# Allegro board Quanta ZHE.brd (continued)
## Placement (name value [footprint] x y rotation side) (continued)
TP56  *TP  [TP2050]  42.35 55.42 180 bottom
TP57  *TP  [TP2650]  36.23 47.62 180 bottom
TP58  *TP  [TP2650]  35.72 46.4 180 bottom
TP59  *TP  [TP2650]  25.69 44.88 180 bottom
TP60  *TP  [TP2650]  26.19 43.48 180 bottom
TP61  *TP  [TP2050]  15.78 23.16 180 bottom
TP62  *TP  [TP2050]  72.8 66.22 0 top
TP63  *TP  [TP2050]  43.72 33.86 0 top
U1  AZ1045-04F.R7G  [UDFN10-2_5X1-5]  118.52 94.41 180 top
U2  AZ1045-04F.R7G  [UDFN10-2_5X1-5]  122.46 94.41 180 top
U3  RTL8111H-CG  [QFN32-4X4-4-33P-0_9H]  30.64 89.84 90 top
U4  G524B2T11U  [SOT23-5]  90.2 89.2 180 top
U5  AZ1065-06F.R7G  [DFN10-4_1X2-8-11P]  102.9 88.82 180 top
U6  PS8209AQFN48GTR2-A0  [QFN48-6X6-4-49P-PS8409]  119.67 84.12 90 top
U7  G5245AT11U  [SOT23-5-2_8-95-5P-G708]  155.61 78.66 0 top
U8  AZ1065-06F.R7G  [DFN10-4_1X2-8-11P]  168.94 59.74 90 top
U9  RAM@DDR4_96P  [BGA96-MICRON-MT41J64M16JT-187EG]  137.58 55.11 90 top
U10  *G2129TL1U  [SC70-2_1-65-6P-G2129TL1U]  21.75 44.75 270 top
U11  RTS5170-GRT  [QFN24-4X4-5-25P-ALC5629]  164.88 43.23 270 top
U12  *G9090-180T11U  [TSOT23-2_8-95-5P-G916-475TOUF]  47.15 42.34 90 top
U13  RAM@DDR4_96P  [BGA96-MICRON-MT41J64M16JT-187EG]  137.58 37.33 90 top
U14  IT8987E/BX  [LQFP128-16X16-4-1_6H]  30.51 32.18 270 top
U15  *G923-330T1UF  [SOT23-5]  173.36 31.04 180 top
U16  ALC255-CG  [QFN48-6X6-4-49P-ALC280]  179.48 17.99 0 top
U17  GS@LIS3DHTR  [LGA16-3X3-5]  95.54 13.26 270 top
U18  G524B2T11U  [SOT23-5]  114.97 94.66 180 bottom
U19  AP2331SA-7  [SOT23_213-3_3-2]  118.78 93.39 90 bottom
U20  NS892407  [TRF-15_1X10-1-25P]  40.29 92.12 90 bottom
U21  GD25LB64CSIGR  [SOIC8-7_9-1_27-2_16H]  85.73 88.06 90 bottom
U22  GLK_SOC_RVP1  [BGA1090-INTEL-GEMINI-LAKE]  97.78 63.65 270 bottom
U23  *TPM@G2129TL1U  [SC70-2_1-65-6P-G2129TL1U]  42.07 58.34 0 bottom
U24  G524B2T11U  [SOT23-5]  167.16 55.17 0 bottom
U25  RAM@DDR4_96P  [BGA96-MICRON-MT41J64M16JT-187EG]  137.58 55.11 270 bottom
U26  EM@H26M64103EMR  [BGA153-SANDISK-SDIN7DP4-16G]  62.14 53.49 270 bottom
U27  G753T11U  [SOT23-5-2_8-95-5P-G708]  54.11 54.02 90 bottom
U28  *TPM@NPCT650ABAYX  [QFN32-5X5-5-33P-0_85H]  41.82 51.36 270 bottom
U29  W25X10CLSNIG  [SOIC8-6-1_27]  30.64 45.19 270 bottom
U30  RAM@DDR4_96P  [BGA96-MICRON-MT41J64M16JT-187EG]  137.58 37.33 270 bottom
U31  APL5606AKI-TRG  [SOP8-6-1_27-G5461]  25.69 31.29 90 bottom
U32  PS8527BTQFN20GTR2-A2  [TQFN20-4X4-5-25P]  129.95 24.18 270 bottom
U33  G2129BTL1U  [SC70-2_1-65-6P-G2129TL1U]  42.2 15.67 90 bottom
U34  *MC74VHC1G08DFT2G  [SOT353-1-2_125-65-5P]  61.25 61.9 0 top
Y1  25MHZ/30ppm  [XTL-2_05X1_65-1_4X1_1-0_6H]  30.64 82.47 0 top
Y2  32.768KHZ/20ppm  [XTL-3_2X1_5-2_5-0_8H]  100.49 82.85 0 bottom
Y3  19.2MHZ/20ppm  [XTL-3_2X2_5-2_2X1_7-0_8H]  117.5 68.27 90 bottom

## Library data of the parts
C1 C2 C4-C37 C39 C40 C42-C52 C54-C62 C64 C66 C67 C69-C76 C78 C80-C82 C84-C109 C111-C159 C161-C170 C172-C181 C183-C257 C259-C261 C263-C272 C274-C302 C304-C331 C333-C350 C353-C436 C438-C470 C473-C481 C483-C485 C487 C488 C542 PC1 PC2 PC7-PC11 PC16-PC23 PC25-PC28 PC31-PC33 PC36-PC38 PC41-PC48 PC51 PC56 PC60 PC62-PC64 PC66 PC68-PC72 PC74 PC76-PC78 PC80-PC83 PC85-PC111 PC118-PC128 PC133-PC152 PC155 PC156 PC159-PC165 PC168-PC174 PC177-PC196 PC200 PC211 PC214 PC216 PC220-PC229 PC232-PC235 PC237 = CAP NON-POL_BGM
C3 C38 C41 C53 C63 C65 C68 C77 C79 C83 C110 C258 C262 C273 C437 C471 C472 C482 PC3-PC6 PC12-PC15 PC24 PC29 PC30 PC34 PC35 PC39 PC40 PC49 PC50 PC52-PC55 PC57-PC59 PC61 PC65 PC67 PC73 PC75 PC79 PC84 PC112-PC117 PC129-PC132 PC153 PC154 PC157 PC158 PC166 PC167 PC175 PC176 PC197-PC199 PC201-PC203 PC205-PC210 PC212 PC213 PC215 PC217-PC219 PC230 PC231 PC236 = CAP_NON-POL_BGM
C160 C171 C182 C351 C352 = C_11
C332 = C
CN1 = HDMI_C128H9-K1909-L_19P_BGM
CN2 CN6 = USB3_13P_BGM
CN3 = USB2_8P_BGM
CN4 = RJ45_8P_4F_BGM
CN5 = Housing_40P_6fixP_BGM
CN7 = CON30X1_0
CN8 = COMBOJACK_7P_BGM
CN9 CN13 CN17 = FFCFPC_4P_BGM
CN10 = NGFF_79P_EKEY_NAME_BGM
CN11 = SDCARD_17P_156-2001902600_BGM
CN12 = FFCFPC_8P_BGM
CN14 = RTC_4P_BGM
CN15 = Housing_20P_FIX6P_BGM
CN16 = CON26_0
CP1-CP6 = CAP_8P4R_BGM
D1 D2 D7 D15 D16 D24 D28 D30 D37 D38 D41 = TVS_DIODE_BGM
D3 D4 D6 D8-D11 D14 D17 D18 D21 D22 D26 D27 D31 D32 D35 D36 D39 = Schottky_DIODE_BGM
D5 = DIODE_BGM
D12 D13 D19 D20 D23 D25 = TVS_DIODE_BGM_0
D29 = BAT54C_BGM
D40 EC1-EC6 = Varistor_BGM
ESD2 = AZC099-04S.R_BGM
HE1 = HALL_IC_3P_BGM
HOLE1 HOLE5 HOLE6 HOLE8-HOLE10 = 3x2_0.1
HOLE2-HOLE4 HOLE7 HOLE11-HOLE17 SPAD1-SPAD10 = 3x2_1.1
J1 = OPEN
JDIM1 = DDR4_264P_BGM
L1 L3 L9 PR1-PR101 PR104-PR110 PR112-PR128 PR130-PR133 PR135 PR137-PR149 PR151 PR152 PR154-PR158 PR161-PR164 PR166-PR192 PR194-PR202 PR204-PR258 PR260-PR264 R1-R75 R77-R82 R84 R86-R94 R96-R104 R106-R115 R117-R119 R123 R125-R143 R145 R146 R148-R241 R243-R263 R265-R287 R289-R309 R311-R530 R532 R534-R554 R556 R558-R582 R584-R631 R633 R634 R636-R638 = RES_BGM
L2 L4-L8 L10 = BEAD_BGM
L11 = BW_BGM
L12 PL1-PL10 = INDUCTOR_BGM
LED1 LED2 = LED_4P_1423_B_O_BGM
PC204 = CAP POL_BGM
PD1-PD3 = ZENER_DIODE_BGM
PD4 = SV1040_3P_BGM
PJ1-PJ4 PJ6-PJ15 PR150 PR259 R95 = R_Current_SEN_BGM
PJ5 = Single_4P_NOFIX_BGM
PJ16 = Header_8P_BGM
PQ1 PQ3 PQ5 PQ7-PQ9 PQ11 PQ24 Q4 Q11-Q13 Q17-Q19 Q21 Q22 Q24 Q30 Q33 Q34 Q37 Q38 = MOS-N_3P_ESD_BGM
PQ2 PQ10 PQ19 = MOS-N_3P_BGM
PQ4 PQ12 Q1 Q5 Q27 = DTC144EU_BGM
PQ6 = MOS-P_3P_ESD_BGM
PQ13 PQ14 PQ17 PQ18 PQ21-PQ23 = MOS-N_8P_BGM
PQ15 PQ16 PQ20 = MOS-N_8P_SCH_BGM
PR134 PR136 PR159 PR160 = Thermistor_BGM
PU1 PU10 = RT3601EAGQW_BGM
PU2 = BQ24780SRUYR_BGM
PU3 PU11 = G5719CTB1U_BGM
PU4 PU9 = AOZ1331DI_BGM
PU5 = TMP708_BGM
PU6 = G5335QT2U_BGM
PU7 = M5671RE1U_BGM
PU8 = TPS61087DRCR_BGM
PU12 = G9661-25ADJF12U_BGM
PU13 = RT6256BGQUF_12P_BGM
PU14 = RT6258CGQUF_12P_BGM
PU15 = RT8231BGQW_BGM
Q2 Q7 Q15 Q16 Q20 Q23 Q26 Q29 Q31 Q32 Q35 = MOS-N_Dual_6P_ESD_BGM
Q3 Q14 Q25 Q36 = MOS-P_3P_BGM
Q28 = NPN_BGM
R85 R583 = R-0603
R144 R147 R242 R264 R310 R531 R533 R555 R557 = SHORTPAD_BGM
RP1 = RES_10P8R_BGM
SW1 SW3 = SW_6P_BGM
SW2 = SW_6P_R_BGM
TP1-TP10 TP12-TP63 = TP_BGM
U1 U2 = G995_1
U3 = RTL8111HSH-CG_BGM
U4 U18 U24 = G524B2T11U_BGM
U5 U8 = AZ1065-06F.R7G_10P-BGM
U6 = PS8409AQFN48GTR2-A0_48P_BGM
U7 = G5245AT11U_BGM
U9 U13 U25 U30 = DDR4_96P_BGM
U10 U23 = G2129TL1U_BGM
U11 = RTS5170-GRT_BGM
U12 = G9090-180T11U_BGM
U14 = IT8987E/BX_BGM
U15 = G923-330T1UF_BGM
U16 = ALC255-CG_BGM
U17 = LIS3DHTR_BGM
U19 = AP2331SA-7-01_BGM
U20 = A-1010G_BGM
U21 = SPI_GD25LB64CSIGR_BGM
U22 = GLK_SOC_RVP1
U26 = EMMC_153P_H26M64103EMR_BGM_2
U27 = G753T11U_BGM
U28 = NPCT650ABAYX_BGM
U29 = W25X10CLSNIG_BGM_2
U31 = G991P11U_BGM
U32 = PS8527BTQFN20GTR2-A2_BGM
U33 = G2129BTL1U_BGM
U34 = MC74VHC1G08DFT2G_5P_BGM
Y1 Y3 = CRYSTAL_4P_BGM
Y2 = CRYSTAL_2P_BGM

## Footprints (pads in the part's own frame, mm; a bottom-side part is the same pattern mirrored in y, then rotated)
8P4R
  rect 0.406x1.092 smd: 1(-1.194,-0.8) 2(-1.194,0.8) 3(-0.406,-0.8) 4(-0.406,0.8) 5(0.406,-0.8) 6(0.406,0.8) 7(1.194,-0.8) 8(1.194,0.8)
10P8R
  rect 0.305x1.092 smd: 1(-1.27,-0.85) 2(-0.635,-0.85) 3(0,-0.85) 4(0.635,-0.85) 5(1.27,-0.85) 6(1.27,0.85) 7(0.635,0.85) 8(0,0.85) 9(-0.635,0.85) 10(-1.27,0.85)
50271-0040N-V01-4P-L
  rect 0.787x1.6 smd: 1(-1.875,2.9) 2(-0.625,2.9) 3(0.625,2.9) 4(1.875,2.9)
  rect 2.108x2.997 smd: 5(-4.425,0) 6(4.425,0)
50320-0040N-001-4P-L-SMT
  round 1.422 hole 1.016: 1(-3.75,2.9) 2(-1.25,2.9) 3(1.25,2.9) 4(3.75,2.9)
50458-00801-V02-8P-L
  rect 0.559x1.295 smd: 1(-7,5.025) 2(-5,5.025) 3(-3,5.025) 4(-1,5.025) 5(1,5.025) 6(3,5.025) 7(5,5.025) 8(7,5.025)
  rect 1.295x2.057 smd: 9(-10.1,0) 10(10.1,0)
50584-0280N-V01-28P-L
  rect 0.61x1.092 smd: 1(-13.5,2.05) 2(-12.5,2.05) 3(-11.5,2.05) 4(-10.5,2.05) 5(-9.5,2.05) 6(-8.5,2.05) 7(-7.5,2.05) 8(-6.5,2.05) 9(-5.5,2.05) 10(-4.5,2.05) 11(-3.5,2.05) 12(-2.5,2.05) 13(-1.5,2.05) 14(-0.5,2.05) 15(0.5,2.05) 16(1.5,2.05) 17(2.5,2.05) 18(3.5,2.05) 19(4.5,2.05) 20(5.5,2.05) 21(6.5,2.05) 22(7.5,2.05) 23(8.5,2.05) 24(9.5,2.05) 25(10.5,2.05) 26(11.5,2.05) 27(12.5,2.05) 28(13.5,2.05)
  rect 2.159x2.997 smd: 29(-15.975,0) 30(15.975,0)
51653-0080N-001-8P-L
  rect 0.508x1.295 smd: 1(-3.5,2.8) 2(-2.5,2.8) 3(-1.5,2.8) 4(-0.5,2.8) 5(0.5,2.8) 6(1.5,2.8) 7(2.5,2.8) 8(3.5,2.8)
  rect 1.803x1.397 smd: 9(-5.65,0) 10(5.65,0)
51653-00401-V01-4P-L
  rect 0.305x1.295 smd: 1(-1.5,2.65) 2(-0.5,2.65) 3(0.5,2.65) 4(1.5,2.65)
  rect 1.803x1.397 smd: 5(-3.65,0) 6(3.65,0)
88511-180N-18P-L
  rect 0.305x1.295 smd: 1(-4.25,2.8) 2(-3.75,2.8) 3(-3.25,2.8) 4(-2.75,2.8) 5(-2.25,2.8) 6(-1.75,2.8) 7(-1.25,2.8) 8(-0.75,2.8) 9(-0.25,2.8) 10(0.25,2.8) 11(0.75,2.8) 12(1.25,2.8) 13(1.75,2.8) 14(2.25,2.8) 15(2.75,2.8) 16(3.25,2.8) 17(3.75,2.8) 18(4.25,2.8)
  rect 1.803x1.397 smd: 19(-5.9,0) 20(5.9,0)
AUDIO-2SJ3108-072111F-6P
  oval 0.991x1.702 hole 0.61x1.295: 1(-4.5,6.35) 2(-4.5,1.35) 3(-4.5,-1.25) 4(4.5,-1.5) 6(4.5,1.15) 7(4.5,3.75)
  oval 0.991x1.6 hole 0.61x1.194: 5(4.5,6.9)
BAT-AAA-BAT-046-K03-2P-SMT
  round 1.194 hole 1.194 unplated: (0,-4)
  round 0.813 hole 0.813 unplated: (0,4)
  rect 2.007x1.499 smd: 1(7.4,0) 2(-7.4,0)
BGA96-MICRON-MT41J64M16JT-187EG
  round 0.356 smd: A1(-3.2,6) A2(-2.4,6) A3(-1.6,6) A7(1.6,6) A8(2.4,6) A9(3.2,6) B1(-3.2,5.2) B2(-2.4,5.2) B3(-1.6,5.2) B7(1.6,5.2) B8(2.4,5.2) B9(3.2,5.2) C1(-3.2,4.4) C2(-2.4,4.4) C3(-1.6,4.4) C7(1.6,4.4) C8(2.4,4.4) C9(3.2,4.4) D1(-3.2,3.6) D2(-2.4,3.6) D3(-1.6,3.6) D7(1.6,3.6) D8(2.4,3.6) D9(3.2,3.6) E1(-3.2,2.8) E2(-2.4,2.8) E3(-1.6,2.8) E7(1.6,2.8) E8(2.4,2.8) E9(3.2,2.8) F1(-3.2,2) F2(-2.4,2) F3(-1.6,2) F7(1.6,2) F8(2.4,2) F9(3.2,2) G1(-3.2,1.2) G2(-2.4,1.2) G3(-1.6,1.2) G7(1.6,1.2) G8(2.4,1.2) G9(3.2,1.2) H1(-3.2,0.4) H2(-2.4,0.4) H3(-1.6,0.4) H7(1.6,0.4) H8(2.4,0.4) H9(3.2,0.4) J1(-3.2,-0.4) J2(-2.4,-0.4) J3(-1.6,-0.4) J7(1.6,-0.4) J8(2.4,-0.4) J9(3.2,-0.4) K1(-3.2,-1.2) K2(-2.4,-1.2) K3(-1.6,-1.2) K7(1.6,-1.2) K8(2.4,-1.2) K9(3.2,-1.2) L1(-3.2,-2) L2(-2.4,-2) L3(-1.6,-2) L7(1.6,-2) L8(2.4,-2) L9(3.2,-2) M1(-3.2,-2.8) M2(-2.4,-2.8) M3(-1.6,-2.8) M7(1.6,-2.8) M8(2.4,-2.8) M9(3.2,-2.8) N1(-3.2,-3.6) N2(-2.4,-3.6) N3(-1.6,-3.6) N7(1.6,-3.6) N8(2.4,-3.6) N9(3.2,-3.6) P1(-3.2,-4.4) P2(-2.4,-4.4) P3(-1.6,-4.4) P7(1.6,-4.4) P8(2.4,-4.4) P9(3.2,-4.4) R1(-3.2,-5.2) R2(-2.4,-5.2) R3(-1.6,-5.2) R7(1.6,-5.2) R8(2.4,-5.2) R9(3.2,-5.2) T1(-3.2,-6) T2(-2.4,-6) T3(-1.6,-6) T7(1.6,-6) T8(2.4,-6) T9(3.2,-6)
BGA153-SANDISK-SDIN7DP4-16G
  round 0.254 smd: A1(-3.25,-3.25) A2(-3.25,-2.75) A3(-3.25,-2.25) A4(-3.25,-1.75) A5(-3.25,-1.25) A6(-3.25,-0.75) A7(-3.25,-0.25) A8(-3.25,0.25) A9(-3.25,0.75) A10(-3.25,1.25) A11(-3.25,1.75) A12(-3.25,2.25) A13(-3.25,2.75) A14(-3.25,3.25) B1(-2.75,-3.25) B2(-2.75,-2.75) B3(-2.75,-2.25) B4(-2.75,-1.75) B5(-2.75,-1.25) B6(-2.75,-0.75) B7(-2.75,-0.25) B8(-2.75,0.25) B9(-2.75,0.75) B10(-2.75,1.25) B11(-2.75,1.75) B12(-2.75,2.25) B13(-2.75,2.75) B14(-2.75,3.25) C1(-2.25,-3.25) C2(-2.25,-2.75) C3(-2.25,-2.25) C4(-2.25,-1.75) C5(-2.25,-1.25) C6(-2.25,-0.75) C7(-2.25,-0.25) C8(-2.25,0.25) C9(-2.25,0.75) C10(-2.25,1.25) C11(-2.25,1.75) C12(-2.25,2.25) C13(-2.25,2.75) C14(-2.25,3.25) D1(-1.75,-3.25) D2(-1.75,-2.75) D3(-1.75,-2.25) D4(-1.75,-1.75) D12(-1.75,2.25) D13(-1.75,2.75) D14(-1.75,3.25) E1(-1.25,-3.25) E2(-1.25,-2.75) E3(-1.25,-2.25) E5(-1.25,-1.25) E6(-1.25,-0.75) E7(-1.25,-0.25) E8(-1.25,0.25) E9(-1.25,0.75) E10(-1.25,1.25) E12(-1.25,2.25) E13(-1.25,2.75) E14(-1.25,3.25) F1(-0.75,-3.25) F2(-0.75,-2.75) F3(-0.75,-2.25) F5(-0.75,-1.25) F10(-0.75,1.25) F12(-0.75,2.25) F13(-0.75,2.75) F14(-0.75,3.25) G1(-0.25,-3.25) G2(-0.25,-2.75) G3(-0.25,-2.25) G5(-0.25,-1.25) G10(-0.25,1.25) G12(-0.25,2.25) G13(-0.25,2.75) G14(-0.25,3.25) H1(0.25,-3.25) H2(0.25,-2.75) H3(0.25,-2.25) H5(0.25,-1.25) H10(0.25,1.25) H12(0.25,2.25) H13(0.25,2.75) H14(0.25,3.25) J1(0.75,-3.25) J2(0.75,-2.75) J3(0.75,-2.25) J5(0.75,-1.25) J10(0.75,1.25) J12(0.75,2.25) J13(0.75,2.75) J14(0.75,3.25) K1(1.25,-3.25) K2(1.25,-2.75) K3(1.25,-2.25) K5(1.25,-1.25) K6(1.25,-0.75) K7(1.25,-0.25) K8(1.25,0.25) K9(1.25,0.75) K10(1.25,1.25) K12(1.25,2.25) K13(1.25,2.75) K14(1.25,3.25) L1(1.75,-3.25) L2(1.75,-2.75) L3(1.75,-2.25) L12(1.75,2.25) L13(1.75,2.75) L14(1.75,3.25) M1(2.25,-3.25) M2(2.25,-2.75) M3(2.25,-2.25) M4(2.25,-1.75) M5(2.25,-1.25) M6(2.25,-0.75) M7(2.25,-0.25) M8(2.25,0.25) M9(2.25,0.75) M10(2.25,1.25) M11(2.25,1.75) M12(2.25,2.25) M13(2.25,2.75) M14(2.25,3.25) N1(2.75,-3.25) N2(2.75,-2.75) N3(2.75,-2.25) N4(2.75,-1.75) N5(2.75,-1.25) N6(2.75,-0.75) N7(2.75,-0.25) N8(2.75,0.25) N9(2.75,0.75) N10(2.75,1.25) N11(2.75,1.75) N12(2.75,2.25) N13(2.75,2.75) N14(2.75,3.25) P1(3.25,-3.25) P2(3.25,-2.75) P3(3.25,-2.25) P4(3.25,-1.75) P5(3.25,-1.25) P6(3.25,-0.75) P7(3.25,-0.25) P8(3.25,0.25) P9(3.25,0.75) P10(3.25,1.25) P11(3.25,1.75) P12(3.25,2.25) P13(3.25,2.75) P14(3.25,3.25)
BGA1090-INTEL-GEMINI-LAKE
  round 0.305 smd: A3(-11.314,-11.03) A4(-11.314,-10.434) A6(-11.314,-9.837) A7(-11.314,-9.062) A50(-11.314,9.588) A51(-11.314,10.185) A53(-11.314,10.795) A54(-11.314,11.405) AA5(-2.349,-10.101) AA7(-2.349,-9.39) AA8(-2.349,-8.679) AA10(-2.349,-7.967) AA12(-2.349,-7.256) AA13(-2.349,-6.545) AA15(-2.349,-5.834) AA17(-2.349,-5.123) AA39(-2.349,5.123) AA41(-2.349,5.834) AA43(-2.349,6.545) AA44(-2.349,7.256) AA46(-2.349,7.967) AA48(-2.349,8.679) AA49(-2.349,9.39) AA51(-2.349,10.101) AC5(-1.397,-10.101) AC7(-1.397,-9.39) AC8(-1.397,-8.679) AC10(-1.397,-7.967) AC12(-1.397,-7.256) AC13(-1.397,-6.545) AC15(-1.397,-5.834) AC17(-1.397,-5.123) AC39(-1.397,5.123) AC41(-1.397,5.834) AC43(-1.397,6.545) AC44(-1.397,7.256) AC46(-1.397,7.967) AC48(-1.397,8.679) AC49(-1.397,9.39) AC51(-1.397,10.101) AE5(-0.521,-10.101) AE7(-0.521,-9.39) AE8(-0.521,-8.679) AE10(-0.521,-7.967) AE12(-0.521,-7.256) AE13(-0.521,-6.545) AE15(-0.521,-5.834) AE17(-0.521,-5.123) AE39(-0.521,5.123) AE41(-0.521,5.834) AE43(-0.521,6.545) AE44(-0.521,7.256) AE46(-0.521,7.967) AE48(-0.521,8.679) AE49(-0.521,9.39) AE51(-0.521,10.101) AF6(0,-9.745) AF8(0,-9.034) AF9(0,-8.323) AF11(0,-7.612) AF12(0,-6.901) AF14(0,-6.189) AF16(0,-5.478) AF40(0,5.478) AF42(0,6.189) AF44(0,6.901) AF45(0,7.612) AF47(0,8.323) AF48(0,9.034) AF50(0,9.745) AG5(0.521,-10.101) AG7(0.521,-9.39) AG8(0.521,-8.679) AG10(0.521,-7.967) AG12(0.521,-7.256) AG13(0.521,-6.545) AG15(0.521,-5.834) AG17(0.521,-5.123) AG39(0.521,5.123) AG41(0.521,5.834) AG43(0.521,6.545) AG44(0.521,7.256) AG46(0.521,7.967) AG48(0.521,8.679) AG49(0.521,9.39) AG51(0.521,10.101) AJ5(1.397,-10.101) AJ7(1.397,-9.39) AJ8(1.397,-8.679) AJ10(1.397,-7.967) AJ12(1.397,-7.256) AJ13(1.397,-6.545) AJ15(1.397,-5.834) AJ17(1.397,-5.123) AJ39(1.397,5.123) AJ41(1.397,5.834) AJ43(1.397,6.545) AJ44(1.397,7.256) AJ46(1.397,7.967) AJ48(1.397,8.679) AJ49(1.397,9.39) AJ51(1.397,10.101) AL5(2.349,-10.101) AL7(2.349,-9.39) AL8(2.349,-8.679) AL10(2.349,-7.967) AL12(2.349,-7.256) AL13(2.349,-6.545) AL15(2.349,-5.834) AL17(2.349,-5.123) AL39(2.349,5.123) AL41(2.349,5.834) AL43(2.349,6.545) AL44(2.349,7.256) AL46(2.349,7.967) AL48(2.349,8.679) AL49(2.349,9.39) AL51(2.349,10.101) AN5(3.226,-10.101) AN7(3.226,-9.39) AN8(3.226,-8.679) AN10(3.226,-7.967) AN12(3.226,-7.256) AN13(3.226,-6.545) AN15(3.226,-5.834) AN17(3.226,-5.123) AN39(3.226,5.123) AN41(3.226,5.834) AN43(3.226,6.545) AN44(3.226,7.256) AN46(3.226,7.967) AN48(3.226,8.679) AN49(3.226,9.39) AN51(3.226,10.101) AR5(3.912,-10.101) AR7(3.912,-9.39) AR8(3.912,-8.679) AR10(3.912,-7.967) AR12(3.912,-7.256) AR13(3.912,-6.545) AR15(3.912,-5.834) AR17(3.912,-5.123) AR39(3.912,5.123) AR41(3.912,5.834) AR43(3.912,6.545) AR44(3.912,7.256) AR46(3.912,7.967) AR48(3.912,8.679) AR49(3.912,9.39) AR51(3.912,10.101) AU5(4.788,-10.101) AU7(4.788,-9.39) AU8(4.788,-8.679) AU10(4.788,-7.967) AU12(4.788,-7.256) AU13(4.788,-6.545) AU15(4.788,-5.834) AU28(4.978,0) AU41(4.788,5.834) AU43(4.788,6.545) AU44(4.788,7.256) AU46(4.788,7.967) AU48(4.788,8.679) AU49(4.788,9.39) AU51(4.788,10.101) AV15(5.333,-5.664) AV17(5.333,-4.788) AV19(5.333,-3.912) AV21(5.333,-3.226) AV23(5.333,-2.349) AV25(5.333,-1.397) AV27(5.333,-0.521) AV29(5.333,0.521) AV31(5.333,1.397) AV33(5.333,2.349) AV35(5.333,3.226) AV37(5.333,3.912) AV39(5.333,4.788) AV41(5.333,5.664) AW5(5.74,-10.101) AW7(5.74,-9.39) AW8(5.74,-8.679) AW10(5.74,-7.967) AW12(5.74,-7.256) AW28(5.689,0) AW44(5.74,7.256) AW46(5.74,7.967) AW48(5.74,8.679) AW49(5.74,9.39) AW51(5.74,10.101) AY13(6.045,-6.693) AY15(6.045,-5.74) AY17(6.045,-4.788) AY19(6.045,-3.912) AY21(6.045,-3.226) AY23(6.045,-2.349) AY25(6.045,-1.397) AY27(6.045,-0.521) AY28(6.4,0) AY29(6.045,0.521) AY31(6.045,1.397) AY33(6.045,2.349) AY35(6.045,3.226) AY37(6.045,3.912) AY39(6.045,4.788) AY41(6.045,5.74) AY43(6.045,6.693) B2(-10.934,-11.434) B55(-10.873,11.814) BA5(6.693,-10.101) BA7(6.693,-9.39) BA8(6.693,-8.679) BA10(6.693,-7.967) BA13(6.756,-6.693) BA15(6.756,-5.74) BA17(6.756,-4.788) BA19(6.756,-3.912) BA21(6.756,-3.226) BA23(6.756,-2.349) BA25(6.756,-1.397) BA27(6.756,-0.521) BA29(6.756,0.521) BA31(6.756,1.397) BA33(6.756,2.349) BA35(6.756,3.226) BA37(6.756,3.912) BA39(6.756,4.788) BA41(6.756,5.74) BA43(6.756,6.693) BA46(6.693,7.967) BA48(6.693,8.679) BA49(6.693,9.39) BA51(6.693,10.101) BB28(7.111,0) BC5(7.645,-10.101) BC7(7.645,-9.39) BC8(7.645,-8.679) BC11(7.467,-7.645) BC13(7.467,-6.693) BC15(7.467,-5.74) BC17(7.467,-4.788) BC19(7.467,-3.912) BC21(7.467,-3.226) BC23(7.467,-2.349) BC25(7.467,-1.397) BC27(7.467,-0.521) BC29(7.467,0.521) BC31(7.467,1.397) BC33(7.467,2.349) BC35(7.467,3.226) BC37(7.467,3.912) BC39(7.467,4.788) BC41(7.467,5.74) BC43(7.467,6.693) BC45(7.467,7.645) BC48(7.645,8.679) BC49(7.645,9.39) BC51(7.645,10.101) BD9(8.178,-8.522) BD11(8.178,-7.645) BD13(8.178,-6.693) BD15(8.178,-5.74) BD17(8.178,-4.788) BD19(8.178,-3.912) BD21(8.178,-3.226) BD23(8.178,-2.349) BD25(8.178,-1.397) BD27(8.178,-0.521) BD28(7.823,0) BD29(8.178,0.521) BD31(8.178,1.397) BD33(8.178,2.349) BD35(8.178,3.226) BD37(8.178,3.912) BD39(8.178,4.788) BD41(8.178,5.74) BD43(8.178,6.693) BD45(8.178,7.645) BD47(8.178,8.522) BE5(8.598,-10.101) BE7(8.598,-9.39) BE28(8.534,0) BE49(8.598,9.39) BE51(8.598,10.101) BF1(9.057,-11.814) BF2(9.125,-11.263) BF9(8.889,-8.598) BF11(8.889,-7.645) BF13(8.889,-6.693) BF15(8.889,-5.74) BF17(8.889,-4.788) BF19(8.889,-3.912) BF21(8.889,-3.226) BF23(8.889,-2.349) BF25(8.889,-1.397) BF27(8.889,-0.521) BF29(8.889,0.521) BF31(8.889,1.397) BF33(8.889,2.349) BF35(8.889,3.226) BF37(8.889,3.912) BF39(8.889,4.788) BF41(8.889,5.74) BF43(8.889,6.693) BF45(8.889,7.645) BF47(8.889,8.598) BF54(9.125,11.263) BF55(9.057,11.814) BG1(9.654,-11.814) BG2(9.671,-11.263) BG4(9.697,-10.676) BG6(9.601,-9.55) BG28(9.245,0) BG50(9.601,9.55) BG52(9.697,10.676) BG54(9.671,11.263) BG55(9.654,11.814) BH1(10.264,-11.814) BH2(10.217,-11.263) BH5(10.215,-10.105) BH6(10.217,-9.553) BH9(9.601,-8.598) BH11(9.601,-7.645) BH13(9.601,-6.693) BH15(9.601,-5.74) BH17(9.601,-4.788) BH19(9.601,-3.912) BH21(9.601,-3.226) BH23(9.601,-2.349) BH25(9.601,-1.397) BH27(9.601,-0.521) BH29(9.601,0.521) BH31(9.601,1.397) BH33(9.601,2.349) BH35(9.601,3.226) BH37(9.601,3.912) BH39(9.601,4.788) BH41(9.601,5.74) BH43(9.601,6.693) BH45(9.601,7.645) BH47(9.601,8.598) BH50(10.217,9.553) BH51(10.215,10.105) BH54(10.217,11.263) BH55(10.264,11.814) BJ2(10.763,-11.263) BJ4(10.763,-10.717) BJ5(10.763,-10.171) BJ6(10.763,-9.625) BJ50(10.763,9.625) BJ51(10.763,10.171) BJ52(10.763,10.717) BJ54(10.763,11.263) BK1(10.873,-11.814) BK55(10.873,11.814) BL2(11.314,-11.405) BL3(11.314,-10.795) BL5(11.314,-10.185) BL6(11.314,-9.588) BL50(11.314,9.588) BL51(11.314,10.185) BL53(11.314,10.795) BL54(11.314,11.405) C1(-10.53,-11.814) C2(-10.369,-11.263) C3(-10.763,-10.87) C5(-10.763,-10.324) C6(-10.763,-9.777) C7(-10.763,-9.231) C50(-10.763,9.625) C51(-10.763,10.171) C52(-10.763,10.717) C54(-10.763,11.263) D1(-9.933,-11.814) D2(-9.823,-11.263) D4(-10.217,-10.692) D6(-10.23,-9.65) D9(-9.601,-8.522) D11(-9.601,-7.645) D13(-9.601,-6.693) D15(-9.601,-5.74) D17(-9.601,-4.788) D19(-9.601,-3.912) D21(-9.601,-3.226) D23(-9.601,-2.349) D25(-9.601,-1.397) D27(-9.601,-0.521) D29(-9.601,0.521) D31(-9.601,1.397) D33(-9.601,2.349) D35(-9.601,3.226) D37(-9.601,3.912) D39(-9.601,4.788) D41(-9.601,5.74) D43(-9.601,6.693) D45(-9.601,7.645) D47(-9.601,8.598) D50(-10.217,9.553) D51(-10.215,10.105) D54(-10.217,11.263) D55(-10.264,11.814) E2(-9.277,-11.263) E5(-9.722,-10.158) E7(-9.696,-9.074) E28(-9.245,0) E50(-9.601,9.55) E52(-9.697,10.676) E54(-9.671,11.263) E55(-9.654,11.814) F1(-9.336,-11.814) F2(-8.731,-11.263) F4(-9.201,-10.692) F6(-9.214,-9.65) F9(-8.889,-8.522) F11(-8.889,-7.645) F13(-8.889,-6.693) F15(-8.889,-5.74) F17(-8.889,-4.788) F19(-8.889,-3.912) F21(-8.889,-3.226) F23(-8.889,-2.349) F25(-8.889,-1.397) F27(-8.889,-0.521) F29(-8.889,0.521) F31(-8.889,1.397) F33(-8.889,2.349) F35(-8.889,3.226) F37(-8.889,3.912) F39(-8.889,4.788) F41(-8.889,5.74) F43(-8.889,6.693) F45(-8.889,7.645) F47(-8.889,8.598) F54(-9.125,11.263) F55(-9.057,11.814) G5(-8.68,-10.158) G7(-8.68,-9.074) G28(-8.534,0) G49(-8.598,9.39) G51(-8.598,10.101) H1(-8.562,-11.814) H4(-8.185,-10.692) H6(-8.198,-9.65) H9(-8.178,-8.522) H11(-8.178,-7.645) H13(-8.178,-6.693) H15(-8.178,-5.74) H17(-8.178,-4.788) H19(-8.178,-3.912) H21(-8.178,-3.226) H23(-8.178,-2.349) H25(-8.178,-1.397) H27(-8.178,-0.521) H28(-7.823,0) H29(-8.178,0.521) H31(-8.178,1.397) H33(-8.178,2.349) H35(-8.178,3.226) H37(-8.178,3.912) H39(-8.178,4.788) H41(-8.178,5.74) H43(-8.178,6.693) H45(-8.178,7.645) H47(-8.178,8.522) J5(-7.569,-10.101) J7(-7.569,-9.39) J8(-7.569,-8.679) J11(-7.467,-7.645) J13(-7.467,-6.693) J15(-7.467,-5.74) J17(-7.467,-4.788) J19(-7.467,-3.912) J21(-7.467,-3.226) J23(-7.467,-2.349) J25(-7.467,-1.397) J27(-7.467,-0.521) J29(-7.467,0.521) J31(-7.467,1.397) J33(-7.467,2.349) J35(-7.467,3.226) J37(-7.467,3.912) J39(-7.467,4.788) J41(-7.467,5.74) J43(-7.467,6.693) J45(-7.467,7.645) J48(-7.645,8.679) J49(-7.645,9.39) J51(-7.645,10.101) K28(-7.111,0) L5(-6.693,-10.101) L7(-6.693,-9.39) L8(-6.693,-8.679) L10(-6.693,-7.967) L13(-6.756,-6.693) L15(-6.756,-5.74) L17(-6.756,-4.788) L19(-6.756,-3.912) L21(-6.756,-3.226) L23(-6.756,-2.349) L25(-6.756,-1.397) L27(-6.756,-0.521) L29(-6.756,0.521) L31(-6.756,1.397) L33(-6.756,2.349) L35(-6.756,3.226) L37(-6.756,3.912) L39(-6.756,4.788) L41(-6.756,5.74) L43(-6.756,6.693) L46(-6.693,7.967) L48(-6.693,8.679) L49(-6.693,9.39) L51(-6.693,10.101) M13(-6.045,-6.693) M15(-6.045,-5.74) M17(-6.045,-4.788) M19(-6.045,-3.912) M21(-6.045,-3.226) M23(-6.045,-2.349) M25(-6.045,-1.397) M27(-6.045,-0.521) M28(-6.4,0) M29(-6.045,0.521) M31(-6.045,1.397) M33(-6.045,2.349) M35(-6.045,3.226) M37(-6.045,3.912) M39(-6.045,4.788) M41(-6.045,5.74) M43(-6.045,6.693) N5(-5.74,-10.101) N7(-5.74,-9.39) N8(-5.74,-8.679) N10(-5.74,-7.967) N12(-5.74,-7.256) N28(-5.689,0) N44(-5.74,7.256) N46(-5.74,7.967) N48(-5.74,8.679) N49(-5.74,9.39) N51(-5.74,10.101) P15(-5.333,-5.664) P17(-5.333,-4.788) P19(-5.333,-3.912) P21(-5.333,-3.226) P23(-5.333,-2.349) P25(-5.333,-1.397) P27(-5.333,-0.521) P29(-5.333,0.521) P31(-5.333,1.397) P33(-5.333,2.349) P35(-5.333,3.226) P37(-5.333,3.912) P39(-5.333,4.788) P41(-5.333,5.664) R5(-4.788,-10.101) R7(-4.788,-9.39) R8(-4.788,-8.679) R10(-4.788,-7.967) R12(-4.788,-7.256) R13(-4.788,-6.545) R15(-4.788,-5.834) R28(-4.978,0) R41(-4.788,5.834) R43(-4.788,6.545) R44(-4.788,7.256) R46(-4.788,7.967) R48(-4.788,8.679) R49(-4.788,9.39) R51(-4.788,10.101) U5(-3.912,-10.101) U7(-3.912,-9.39) U8(-3.912,-8.679) U10(-3.912,-7.967) U12(-3.912,-7.256) U13(-3.912,-6.545) U15(-3.912,-5.834) U17(-3.912,-5.123) U39(-3.912,5.123) U41(-3.912,5.834) U43(-3.912,6.545) U44(-3.912,7.256) U46(-3.912,7.967) U48(-3.912,8.679) U49(-3.912,9.39) U51(-3.912,10.101) W5(-3.226,-10.101) W7(-3.226,-9.39) W8(-3.226,-8.679) W10(-3.226,-7.967) W12(-3.226,-7.256) W13(-3.226,-6.545) W15(-3.226,-5.834) W17(-3.226,-5.123) W39(-3.226,5.123) W41(-3.226,5.834) W43(-3.226,6.545) W44(-3.226,7.256) W46(-3.226,7.967) W48(-3.226,8.679) W49(-3.226,9.39) W51(-3.226,10.101)
  round 0.254 smd: A10(-11.314,-8.115) A12(-11.314,-7.214) A14(-11.314,-6.312) A16(-11.314,-5.41) A18(-11.314,-4.508) A20(-11.314,-3.607) A22(-11.314,-2.705) A24(-11.314,-1.803) A26(-11.314,-0.902) A28(-11.314,0) A30(-11.314,0.902) A32(-11.314,1.803) A34(-11.314,2.705) A36(-11.314,3.607) A38(-11.314,4.508) A40(-11.314,5.41) A42(-11.314,6.312) A44(-11.314,7.214) A46(-11.314,8.115) A48(-11.314,9.017) AA2(-2.254,-11.503) AA3(-2.254,-10.88) AA53(-2.254,10.88) AA54(-2.254,11.503) AB1(-1.803,-11.814) AB3(-1.803,-11.191) AB53(-1.803,11.191) AB55(-1.803,11.814) AC2(-1.353,-11.503) AC3(-1.353,-10.88) AC53(-1.353,10.88) AC54(-1.353,11.503) AD1(-0.902,-11.814) AD3(-0.902,-11.191) AD53(-0.902,11.191) AD55(-0.902,11.814) AE2(-0.451,-11.503) AE3(-0.451,-10.88) AE53(-0.451,10.88) AE54(-0.451,11.503) AF1(0,-11.814) AF3(0,-11.191) AF4(0,-10.569) AF52(0,10.569) AF53(0,11.191) AF55(0,11.814) AG2(0.451,-11.503) AG3(0.451,-10.88) AG53(0.451,10.88) AG54(0.451,11.503) AH1(0.902,-11.814) AH3(0.902,-11.191) AH53(0.902,11.191) AH55(0.902,11.814) AJ2(1.353,-11.503) AJ3(1.353,-10.88) AJ53(1.353,10.88) AJ54(1.353,11.503) AK1(1.803,-11.814) AK3(1.803,-11.191) AK53(1.803,11.191) AK55(1.803,11.814) AL2(2.254,-11.503) AL3(2.254,-10.88) AL53(2.254,10.88) AL54(2.254,11.503) AM1(2.705,-11.814) AM3(2.705,-11.191) AM53(2.705,11.191) AM55(2.705,11.814) AN2(3.156,-11.503) AN3(3.156,-10.88) AN53(3.156,10.88) AN54(3.156,11.503) AP1(3.607,-11.814) AP3(3.607,-11.191) AP53(3.607,11.191) AP55(3.607,11.814) AR2(4.058,-11.503) AR3(4.058,-10.88) AR53(4.058,10.88) AR54(4.058,11.503) AT1(4.508,-11.814) AT3(4.508,-11.191) AT53(4.508,11.191) AT55(4.508,11.814) AU2(4.959,-11.503) AU3(4.959,-10.88) AU53(4.959,10.88) AU54(4.959,11.503) AV1(5.41,-11.814) AV3(5.41,-11.191) AV53(5.41,11.191) AV55(5.41,11.814) AW2(5.861,-11.503) AW3(5.861,-10.88) AW53(5.861,10.88) AW54(5.861,11.503) AY1(6.312,-11.814) AY3(6.312,-11.191) AY53(6.312,11.191) AY55(6.312,11.814) B9(-11.003,-8.566) B11(-11.003,-7.664) B13(-11.003,-6.763) B15(-11.003,-5.861) B17(-11.003,-4.959) B19(-11.003,-4.058) B21(-11.003,-3.156) B23(-11.003,-2.254) B25(-11.003,-1.353) B27(-11.003,-0.451) B29(-11.003,0.451) B31(-11.003,1.353) B33(-11.003,2.254) B35(-11.003,3.156) B37(-11.003,4.058) B39(-11.003,4.959) B41(-11.003,5.861) B43(-11.003,6.763) B45(-11.003,7.664) B47(-11.003,8.566) BA2(6.763,-11.503) BA3(6.763,-10.88) BA53(6.763,10.88) BA54(6.763,11.503) BB1(7.214,-11.814) BB3(7.214,-11.191) BB53(7.214,11.191) BB55(7.214,11.814) BC2(7.664,-11.503) BC3(7.664,-10.88) BC53(7.664,10.88) BC54(7.664,11.503) BD1(8.115,-11.814) BD3(8.115,-11.191) BD53(8.115,11.191) BD55(8.115,11.814) BE2(8.566,-11.503) BE3(8.566,-10.88) BE53(8.566,10.88) BE54(8.566,11.503) BH28(10.068,0) BJ8(10.691,-9.017) BJ9(10.38,-8.566) BJ10(10.691,-8.115) BJ11(10.38,-7.664) BJ12(10.691,-7.214) BJ13(10.38,-6.763) BJ14(10.691,-6.312) BJ15(10.38,-5.861) BJ16(10.691,-5.41) BJ17(10.38,-4.959) BJ18(10.691,-4.508) BJ19(10.38,-4.058) BJ20(10.691,-3.607) BJ21(10.38,-3.156) BJ22(10.691,-2.705) BJ23(10.38,-2.254) BJ24(10.691,-1.803) BJ25(10.38,-1.353) BJ26(10.691,-0.902) BJ27(10.38,-0.451) BJ28(10.691,0) BJ29(10.38,0.451) BJ30(10.691,0.902) BJ31(10.38,1.353) BJ32(10.691,1.803) BJ33(10.38,2.254) BJ34(10.691,2.705) BJ35(10.38,3.156) BJ36(10.691,3.607) BJ37(10.38,4.058) BJ38(10.691,4.508) BJ39(10.38,4.959) BJ40(10.691,5.41) BJ41(10.38,5.861) BJ42(10.691,6.312) BJ43(10.38,6.763) BJ44(10.691,7.214) BJ45(10.38,7.664) BJ46(10.691,8.115) BJ47(10.38,8.566) BJ48(10.691,9.017) BK9(11.003,-8.566) BK11(11.003,-7.664) BK13(11.003,-6.763) BK15(11.003,-5.861) BK17(11.003,-4.959) BK19(11.003,-4.058) BK21(11.003,-3.156) BK23(11.003,-2.254) BK25(11.003,-1.353) BK27(11.003,-0.451) BK29(11.003,0.451) BK31(11.003,1.353) BK33(11.003,2.254) BK35(11.003,3.156) BK37(11.003,4.058) BK39(11.003,4.959) BK41(11.003,5.861) BK43(11.003,6.763) BK45(11.003,7.664) BK47(11.003,8.566) BL8(11.314,-9.017) BL10(11.314,-8.115) BL12(11.314,-7.214) BL14(11.314,-6.312) BL16(11.314,-5.41) BL18(11.314,-4.508) BL20(11.314,-3.607) BL22(11.314,-2.705) BL24(11.314,-1.803) BL26(11.314,-0.902) BL28(11.314,0) BL30(11.314,0.902) BL32(11.314,1.803) BL34(11.314,2.705) BL36(11.314,3.607) BL38(11.314,4.508) BL40(11.314,5.41) BL42(11.314,6.312) BL44(11.314,7.214) BL46(11.314,8.115) BL48(11.314,9.017) C9(-10.38,-8.566) C10(-10.691,-8.115) C11(-10.38,-7.664) C12(-10.691,-7.214) C13(-10.38,-6.763) C14(-10.691,-6.312) C15(-10.38,-5.861) C16(-10.691,-5.41) C17(-10.38,-4.959) C18(-10.691,-4.508) C19(-10.38,-4.058) C20(-10.691,-3.607) C21(-10.38,-3.156) C22(-10.691,-2.705) C23(-10.38,-2.254) C24(-10.691,-1.803) C25(-10.38,-1.353) C26(-10.691,-0.902) C27(-10.38,-0.451) C28(-10.691,0) C29(-10.38,0.451) C30(-10.691,0.902) C31(-10.38,1.353) C32(-10.691,1.803) C33(-10.38,2.254) C34(-10.691,2.705) C35(-10.38,3.156) C36(-10.691,3.607) C37(-10.38,4.058) C38(-10.691,4.508) C39(-10.38,4.959) C40(-10.691,5.41) C41(-10.38,5.861) C42(-10.691,6.312) C43(-10.38,6.763) C44(-10.691,7.214) C45(-10.38,7.664) C46(-10.691,8.115) C47(-10.38,8.566) C48(-10.691,9.017) D28(-10.068,0) G53(-8.566,10.88) G54(-8.566,11.503) H2(-8.152,-11.246) H53(-8.115,11.191) H55(-8.115,11.814) J2(-7.664,-11.503) J3(-7.664,-10.88) J53(-7.664,10.88) J54(-7.664,11.503) K1(-7.214,-11.814) K3(-7.214,-11.191) K53(-7.214,11.191) K55(-7.214,11.814) L2(-6.763,-11.503) L3(-6.763,-10.88) L53(-6.763,10.88) L54(-6.763,11.503) M1(-6.312,-11.814) M3(-6.312,-11.191) M53(-6.312,11.191) M55(-6.312,11.814) N2(-5.861,-11.503) N3(-5.861,-10.88) N53(-5.861,10.88) N54(-5.861,11.503) P1(-5.41,-11.814) P3(-5.41,-11.191) P53(-5.41,11.191) P55(-5.41,11.814) R2(-4.959,-11.503) R3(-4.959,-10.88) R53(-4.959,10.88) R54(-4.959,11.503) T1(-4.508,-11.814) T3(-4.508,-11.191) T53(-4.508,11.191) T55(-4.508,11.814) U2(-4.058,-11.503) U3(-4.058,-10.88) U53(-4.058,10.88) U54(-4.058,11.503) V1(-3.607,-11.814) V3(-3.607,-11.191) V53(-3.607,11.191) V55(-3.607,11.814) W2(-3.156,-11.503) W3(-3.156,-10.88) W53(-3.156,10.88) W54(-3.156,11.503) Y1(-2.705,-11.814) Y3(-2.705,-11.191) Y53(-2.705,11.191) Y55(-2.705,11.814)
  round 0.33 smd: AA18(-2.172,-4.572) AA20(-2.172,-3.81) AA21(-2.172,-3.048) AA23(-2.172,-2.286) AA25(-2.172,-1.524) AA27(-2.172,-0.762) AA28(-2.172,0) AA29(-2.172,0.762) AA31(-2.172,1.524) AA33(-2.172,2.286) AA35(-2.172,3.048) AA36(-2.172,3.81) AA38(-2.172,4.572) AC18(-1.448,-4.572) AC20(-1.448,-3.81) AC21(-1.448,-3.048) AC23(-1.448,-2.286) AC25(-1.448,-1.524) AC27(-1.448,-0.762) AC28(-1.448,0) AC29(-1.448,0.762) AC31(-1.448,1.524) AC33(-1.448,2.286) AC35(-1.448,3.048) AC36(-1.448,3.81) AC38(-1.448,4.572) AE18(-0.724,-4.572) AE20(-0.724,-3.81) AE21(-0.724,-3.048) AE23(-0.724,-2.286) AE25(-0.724,-1.524) AE27(-0.724,-0.762) AE28(-0.724,0) AE29(-0.724,0.762) AE31(-0.724,1.524) AE33(-0.724,2.286) AE35(-0.724,3.048) AE36(-0.724,3.81) AE38(-0.724,4.572) AF18(0,-4.572) AF20(0,-3.81) AF21(0,-3.048) AF23(0,-2.286) AF25(0,-1.524) AF27(0,-0.762) AF28(0,0) AF29(0,0.762) AF31(0,1.524) AF33(0,2.286) AF35(0,3.048) AF36(0,3.81) AF38(0,4.572) AG18(0.724,-4.572) AG20(0.724,-3.81) AG21(0.724,-3.048) AG23(0.724,-2.286) AG25(0.724,-1.524) AG27(0.724,-0.762) AG28(0.724,0) AG29(0.724,0.762) AG31(0.724,1.524) AG33(0.724,2.286) AG35(0.724,3.048) AG36(0.724,3.81) AG38(0.724,4.572) AJ18(1.448,-4.572) AJ20(1.448,-3.81) AJ21(1.448,-3.048) AJ23(1.448,-2.286) AJ25(1.448,-1.524) AJ27(1.448,-0.762) AJ28(1.448,0) AJ29(1.448,0.762) AJ31(1.448,1.524) AJ33(1.448,2.286) AJ35(1.448,3.048) AJ36(1.448,3.81) AJ38(1.448,4.572) AL18(2.172,-4.572) AL20(2.172,-3.81) AL21(2.172,-3.048) AL23(2.172,-2.286) AL25(2.172,-1.524) AL27(2.172,-0.762) AL28(2.172,0) AL29(2.172,0.762) AL31(2.172,1.524) AL33(2.172,2.286) AL35(2.172,3.048) AL36(2.172,3.81) AL38(2.172,4.572) AM18(2.896,-4.572) AM20(2.896,-3.81) AM21(2.896,-3.048) AM23(2.896,-2.286) AM25(2.896,-1.524) AM27(2.896,-0.762) AM28(2.896,0) AM29(2.896,0.762) AM31(2.896,1.524) AM33(2.896,2.286) AM35(2.896,3.048) AM36(2.896,3.81) AM38(2.896,4.572) AP18(3.619,-4.572) AP20(3.619,-3.81) AP21(3.619,-3.048) AP23(3.619,-2.286) AP25(3.619,-1.524) AP27(3.619,-0.762) AP28(3.619,0) AP29(3.619,0.762) AP31(3.619,1.524) AP33(3.619,2.286) AP35(3.619,3.048) AP36(3.619,3.81) AP38(3.619,4.572) AT18(4.343,-4.572) AT20(4.343,-3.81) AT21(4.343,-3.048) AT23(4.343,-2.286) AT25(4.343,-1.524) AT27(4.343,-0.762) AT28(4.343,0) AT29(4.343,0.762) AT31(4.343,1.524) AT33(4.343,2.286) AT35(4.343,3.048) AT36(4.343,3.81) AT38(4.343,4.572) T18(-4.343,-4.572) T20(-4.343,-3.81) T21(-4.343,-3.048) T23(-4.343,-2.286) T25(-4.343,-1.524) T27(-4.343,-0.762) T28(-4.343,0) T29(-4.343,0.762) T31(-4.343,1.524) T33(-4.343,2.286) T35(-4.343,3.048) T36(-4.343,3.81) T38(-4.343,4.572) V18(-3.619,-4.572) V20(-3.619,-3.81) V21(-3.619,-3.048) V23(-3.619,-2.286) V25(-3.619,-1.524) V27(-3.619,-0.762) V28(-3.619,0) V29(-3.619,0.762) V31(-3.619,1.524) V33(-3.619,2.286) V35(-3.619,3.048) V36(-3.619,3.81) V38(-3.619,4.572) Y18(-2.896,-4.572) Y20(-2.896,-3.81) Y21(-2.896,-3.048) Y23(-2.896,-2.286) Y25(-2.896,-1.524) Y27(-2.896,-0.762) Y28(-2.896,0) Y29(-2.896,0.762) Y31(-2.896,1.524) Y33(-2.896,2.286) Y35(-2.896,3.048) Y36(-2.896,3.81) Y38(-2.896,4.572)
C0402
  custom 0.12x0.12 smd: 1(0.39,0) 2(-0.39,0)
C0402_2
  custom 0.12x0.12 smd: 1(0.39,0) 2(-0.39,0)
C0603
  rect 0.686x0.813 smd: 1(0.6,0) 2(-0.6,0)
C0805
  rect 0.864x1.372 smd: 1(0.88,0) 2(-0.88,0)
C1206
  rect 1.219x1.626 smd: 1(1.4,0) 2(-1.4,0)
CC1808
  rect 2.159x2.286 smd: 1(-2.349,0) 2(2.349,0)
CHOKE-PCMC063T-3R3MN-SMT
  rect 1.854x3.505 smd: 1(-3.275,0) 2(3.275,0)
D-2_8X1_78
  rect 2.21x1.397 smd: 1(-0.95,0)
  rect 0.889x1.397 smd: 2(1.6,0)
D-3_8X2_5
  rect 1.6x1.905 smd: 1(-2.15,0) 2(2.15,0)
D-TO277_213-6_1X4_3
  rect 1.168x1.397 smd: 1(3.885,1.05) 2(3.885,-1.05)
  rect 4.648x3.505 smd: 3(0,0)
DDR4-D4AR0-26001-1P52-RVS-SMT
  round 1.092 hole 1.092 unplated: (-34.4,0)
  round 1.6 hole 1.6 unplated: (34.4,0)
  rect 0.254x1.753 smd: 1(33.375,4.1) 2(33.125,-4.1) 3(32.875,4.1) 4(32.625,-4.1) 5(32.375,4.1) 6(32.125,-4.1) 7(31.875,4.1) 8(31.625,-4.1) 9(31.375,4.1) 10(31.125,-4.1) 11(30.875,4.1) 12(30.625,-4.1) 13(30.375,4.1) 14(30.125,-4.1) 15(29.875,4.1) 16(29.625,-4.1) 17(29.375,4.1) 18(29.125,-4.1) 19(28.875,4.1) 20(28.625,-4.1) 21(28.375,4.1) 22(28.125,-4.1) 23(27.875,4.1) 24(27.625,-4.1) 25(27.375,4.1) 26(27.125,-4.1) 27(26.875,4.1) 28(26.625,-4.1) 29(26.375,4.1) 30(26.125,-4.1) 31(25.875,4.1) 32(25.625,-4.1) 33(25.375,4.1) 34(25.125,-4.1) 35(24.875,4.1) 36(24.625,-4.1) 37(24.375,4.1) 38(24.125,-4.1) 39(23.875,4.1) 40(23.625,-4.1) 41(23.375,4.1) 42(23.125,-4.1) 43(22.875,4.1) 44(22.625,-4.1) 45(22.375,4.1) 46(22.125,-4.1) 47(21.875,4.1) 48(21.625,-4.1) 49(21.375,4.1) 50(21.125,-4.1) 51(20.875,4.1) 52(20.625,-4.1) 53(20.375,4.1) 54(20.125,-4.1) 55(19.875,4.1) 56(19.625,-4.1) 57(19.375,4.1) 58(19.125,-4.1) 59(18.875,4.1) 60(18.625,-4.1) 61(18.375,4.1) 62(18.125,-4.1) 63(17.875,4.1) 64(17.625,-4.1) 65(17.375,4.1) 66(17.125,-4.1) 67(16.875,4.1) 68(16.625,-4.1) 69(16.375,4.1) 70(16.125,-4.1) 71(15.875,4.1) 72(15.625,-4.1) 73(15.375,4.1) 74(15.125,-4.1) 75(14.875,4.1) 76(14.625,-4.1) 77(14.375,4.1) 78(14.125,-4.1) 79(13.875,4.1) 80(13.625,-4.1) 81(13.375,4.1) 82(13.125,-4.1) 83(12.875,4.1) 84(12.625,-4.1) 85(12.375,4.1) 86(12.125,-4.1) 87(11.875,4.1) 88(11.625,-4.1) 89(11.375,4.1) 90(11.125,-4.1) 91(10.875,4.1) 92(10.625,-4.1) 93(10.375,4.1) 94(10.125,-4.1) 95(9.875,4.1) 96(9.625,-4.1) 97(9.375,4.1) 98(9.125,-4.1) 99(8.875,4.1) 100(8.625,-4.1) 101(8.375,4.1) 102(8.125,-4.1) 103(7.875,4.1) 104(7.625,-4.1) 105(7.375,4.1) 106(7.125,-4.1) 107(6.875,4.1) 108(6.625,-4.1) 109(6.375,4.1) 110(6.125,-4.1) 111(5.875,4.1) 112(5.625,-4.1) 113(5.375,4.1) 114(5.125,-4.1) 115(4.875,4.1) 116(4.625,-4.1) 117(4.375,4.1) 118(4.125,-4.1) 119(3.875,4.1) 120(3.625,-4.1) 121(3.375,4.1) 122(3.125,-4.1) 123(2.875,4.1) 124(2.625,-4.1) 125(2.375,4.1) 126(2.125,-4.1) 127(1.875,4.1) 128(1.625,-4.1) 129(1.375,4.1) 130(1.125,-4.1) 131(0.875,4.1) 132(0.625,-4.1) 133(0.375,4.1) 134(0.125,-4.1) 135(-0.125,4.1) 136(-0.375,-4.1) 137(-0.625,4.1) 138(-0.875,-4.1) 139(-1.125,4.1) 140(-1.375,-4.1) 141(-1.625,4.1) 142(-1.875,-4.1) 143(-2.125,4.1) 144(-2.375,-4.1) 145(-4.625,4.1) 146(-4.875,-4.1) 147(-5.125,4.1) 148(-5.375,-4.1) 149(-5.625,4.1) 150(-5.875,-4.1) 151(-6.125,4.1) 152(-6.375,-4.1) 153(-6.625,4.1) 154(-6.875,-4.1) 155(-7.125,4.1) 156(-7.375,-4.1) 157(-7.625,4.1) 158(-7.875,-4.1) 159(-8.125,4.1) 160(-8.375,-4.1) 161(-8.625,4.1) 162(-8.875,-4.1) 163(-9.125,4.1) 164(-9.375,-4.1) 165(-9.625,4.1) 166(-9.875,-4.1) 167(-10.125,4.1) 168(-10.375,-4.1) 169(-10.625,4.1) 170(-10.875,-4.1) 171(-11.125,4.1) 172(-11.375,-4.1) 173(-11.625,4.1) 174(-11.875,-4.1) 175(-12.125,4.1) 176(-12.375,-4.1) 177(-12.625,4.1) 178(-12.875,-4.1) 179(-13.125,4.1) 180(-13.375,-4.1) 181(-13.625,4.1) 182(-13.875,-4.1) 183(-14.125,4.1) 184(-14.375,-4.1) 185(-14.625,4.1) 186(-14.875,-4.1) 187(-15.125,4.1) 188(-15.375,-4.1) 189(-15.625,4.1) 190(-15.875,-4.1) 191(-16.125,4.1) 192(-16.375,-4.1) 193(-16.625,4.1) 194(-16.875,-4.1) 195(-17.125,4.1) 196(-17.375,-4.1) 197(-17.625,4.1) 198(-17.875,-4.1) 199(-18.125,4.1) 200(-18.375,-4.1) 201(-18.625,4.1) 202(-18.875,-4.1) 203(-19.125,4.1) 204(-19.375,-4.1) 205(-19.625,4.1) 206(-19.875,-4.1) 207(-20.125,4.1) 208(-20.375,-4.1) 209(-20.625,4.1) 210(-20.875,-4.1) 211(-21.125,4.1) 212(-21.375,-4.1) 213(-21.625,4.1) 214(-21.875,-4.1) 215(-22.125,4.1) 216(-22.375,-4.1) 217(-22.625,4.1) 218(-22.875,-4.1) 219(-23.125,4.1) 220(-23.375,-4.1) 221(-23.625,4.1) 222(-23.875,-4.1) 223(-24.125,4.1) 224(-24.375,-4.1) 225(-24.625,4.1) 226(-24.875,-4.1) 227(-25.125,4.1) 228(-25.375,-4.1) 229(-25.625,4.1) 230(-25.875,-4.1) 231(-26.125,4.1) 232(-26.375,-4.1) 233(-26.625,4.1) 234(-26.875,-4.1) 235(-27.125,4.1) 236(-27.375,-4.1) 237(-27.625,4.1) 238(-27.875,-4.1) 239(-28.125,4.1) 240(-28.375,-4.1) 241(-28.625,4.1) 242(-28.875,-4.1) 243(-29.125,4.1) 244(-29.375,-4.1) 245(-29.625,4.1) 246(-29.875,-4.1) 247(-30.125,4.1) 248(-30.375,-4.1) 249(-30.625,4.1) 250(-30.875,-4.1) 251(-31.125,4.1) 252(-31.375,-4.1) 253(-31.625,4.1) 254(-31.875,-4.1) 255(-32.125,4.1) 256(-32.375,-4.1) 257(-32.625,4.1) 258(-32.875,-4.1) 259(-33.125,4.1) 260(-33.375,-4.1)
  rect 3.505x4.597 smd: 261(33.8,12) 262(-33.8,12)
DFN10-3X3-5-11P-G5318
  rect 0.254x0.711 smd: 1(-1,-1.5) 2(-0.5,-1.5) 3(0,-1.5) 4(0.5,-1.5) 5(1,-1.5) 6(1,1.5) 7(0.5,1.5) 8(0,1.5) 9(-0.5,1.5) 10(-1,1.5)
  rect 2.591x1.6 smd: 11(0,0)
DFN10-4_1X2-8-11P
  rect 0.203x0.61 smd: 1(-1.8,-0.9) 2(-1,-0.9) 3(-0.2,-0.9) 4(0.6,-0.9) 5(1.4,-0.9) 6(1.8,0.9) 7(1,0.9) 8(0.2,0.9) 9(-0.6,0.9) 10(-1.4,0.9)
  rect 1.397x0.787 smd: 11(-0.4,0)
DFN-8L-3X3-65-5P-0_9H
  rect 0.508x0.356 smd: 1(1.4,-0.975) 2(1.4,-0.325) 3(1.4,0.325) 4(1.4,0.975)
  custom 0.57x0.57 smd: 5(-0.51,0)
DSM
  rect 1.016x0.508 smd: 1(-1.3,0) 2(1.321,0)
ECAP6_3X6_1-7_2
  rect 3.505x1.6 smd: 1(2.8,0) 2(-2.8,0)
ESD-1X0_6-2P
  rect 0.559x0.61 smd: 1(-0.425,0) 2(0.425,0)
FILTER-MCM2012B900GBE-4P
  rect 0.762x0.406 smd: 1(-0.925,0.4) 2(0.925,0.4) 3(0.925,-0.4) 4(-0.925,-0.4)
GS12201-1011-9F-20P-L-SMT
  round 0.965 hole 0.965 unplated: (-5.8,0.2) (5.8,0.2)
  rect 0.254x1.143 smd: 1(-4.75,-2.125) 2(-4.25,-2.125) 3(-3.75,-2.125) 4(-3.25,-2.125) 5(-2.75,-2.125) 6(-2.25,-2.125) 7(-1.75,-2.125) 8(-1.25,-2.125) 9(-0.75,-2.125) 10(-0.25,-2.125) 11(0.25,-2.125) 12(0.75,-2.125) 13(1.25,-2.125) 14(1.75,-2.125) 15(2.25,-2.125) 16(2.75,-2.125) 17(3.25,-2.125) 18(3.75,-2.125) 19(4.25,-2.125) 20(4.75,-2.125)
  rect 1.295x1.397 smd: 21(-5.8,-2) 22(5.8,-2) 23(-5.8,2) 24(5.8,2)
GS12401-1011-40P-R-NH-SMT
  round 0.94 hole 0.94 unplated: (-10.5,0) (10.5,0)
  rect 0.254x1.143 smd: 1(9.75,2.125) 2(9.25,2.125) 3(8.75,2.125) 4(8.25,2.125) 5(7.75,2.125) 6(7.25,2.125) 7(6.75,2.125) 8(6.25,2.125) 9(5.75,2.125) 10(5.25,2.125) 11(4.75,2.125) 12(4.25,2.125) 13(3.75,2.125) 14(3.25,2.125) 15(2.75,2.125) 16(2.25,2.125) 17(1.75,2.125) 18(1.25,2.125) 19(0.75,2.125) 20(0.25,2.125) 21(-0.25,2.125) 22(-0.75,2.125) 23(-1.25,2.125) 24(-1.75,2.125) 25(-2.25,2.125) 26(-2.75,2.125) 27(-3.25,2.125) 28(-3.75,2.125) 29(-4.25,2.125) 30(-4.75,2.125) 31(-5.25,2.125) 32(-5.75,2.125) 33(-6.25,2.125) 34(-6.75,2.125) 35(-7.25,2.125) 36(-7.75,2.125) 37(-8.25,2.125) 38(-8.75,2.125) 39(-9.25,2.125) 40(-9.75,2.125)
  rect 1.499x2.997 smd: 41(12.65,0) 42(-12.65,0)
  rect 2.794x1.499 smd: 43(5.7,-2.45) 44(-5.7,-2.45)
H-C94D94N
  round 2.388 hole 2.388 unplated: (0,0)
H-C126D126N
  round 3.2 hole 3.2 unplated: (0,0)
H-C276D138P2
  round 7.01 hole 3.505: 1(0,0)
H-C276D144P2
  round 7.01 hole 3.658: 1(0,0)
H-O94X106D94X106N
  oval 2.388x2.692 hole 2.388x2.692 unplated: (0,0)
H-ZHP-2
  custom 2.625x2.625 hole 2.489: 1(0,0)
HDMI-C128H9-K1909-L-19P
  oval 0.787x0.991 hole 0.508x0.711: 1(-4.5,6.65) 2(-4,8.15) 3(-3.5,6.65) 4(-3,8.15) 5(-2.5,6.65) 6(-2,8.15) 7(-1.5,6.65) 8(-1,8.15) 9(-0.5,6.65) 10(0,8.15) 11(0.5,6.65) 12(1,8.15) 13(1.5,6.65) 14(2,8.15) 15(2.5,6.65) 16(3,8.15) 17(3.5,6.65) 18(4,8.15) 19(4.5,6.65)
  oval 1.397x2.362 hole 0.787x1.753: 20(-9.15,0) 21(-9.15,5) 22(9.15,0) 23(9.15,5)
HG-C276D98P2
  round 7.01 hole 2.489: 1(0,0)
  round 1.016 hole 0.61: 2(0,2.375) 3(1.679,1.679) 4(2.375,0) 5(1.679,-1.679) 6(0,-2.375) 7(-1.679,-1.679) 8(-2.375,0) 9(-1.679,1.679)
HG-NHP-1P
  custom 1.825x1.825 hole 2.489: 1(0,0)
  round 1.016 hole 0.61: 2(0,2.54) 3(1.796,1.796) 4(2.54,0) 5(1.796,-1.796) 6(0,-2.54) 7(-1.796,-1.796) 8(-2.54,0) 9(-1.796,1.796)
HG-ZHP-1
  round 8.992 hole 3.2: 1(0,0)
  round 1.016 hole 0.61: 2(0,2.54) 3(-1.796,1.796) 4(-2.54,0) 5(-1.796,-1.796) 6(0,-2.54) 7(1.796,-1.796) 8(2.54,0) 9(1.796,1.796)
HG-ZHP-2
  round 8.992 hole 3.607: 1(0,0)
  round 1.016 hole 0.61: 2(0,3.15) 3(-2.227,2.227) 4(-3.15,0) 5(-2.227,-2.227) 6(0,-3.15) 7(2.227,-2.227) 8(3.15,0) 9(2.227,2.227)
HG-ZHP-3
  round 8.992 hole 3.2: 1(0,0)
  round 1.016 hole 0.61: 2(0,2.54) 3(-1.796,1.796) 4(-2.54,0) 5(-1.796,-1.796) 6(0,-2.54) 7(1.796,-1.796) 8(2.54,0) 9(1.796,1.796)
JOPEN25X30_S
  custom 0.159x0.159 smd: 1(-0.368,0) 2(0.368,0)
L2_5X2-1_2H
  rect 0.889x2.108 smd: 1(-0.85,0) 2(0.85,0)
L5_1X5_2-1_6H
  rect 1.905x2.489 smd: 1(-2.047,0) 2(2.047,0)
L6_6X6_6-3_8
  rect 2.362x3.505 smd: 1(-3.025,0) 2(3.025,0)
LED19-123-Y2ST1D-C30-2T-4P
  rect 1.092x0.61 smd: 1(0.95,0.45) 2(0.95,-0.45) 3(-0.95,-0.45) 4(-0.95,0.45)
LGA16-3X3-5
  rect 0.305x0.94 smd: 1(-1,-1.525) 2(-0.5,-1.525) 3(0,-1.525) 4(0.5,-1.525) 5(1,-1.525) 9(1,1.525) 10(0.5,1.525) 11(0,1.525) 12(-0.5,1.525) 13(-1,1.525)
  rect 0.94x0.305 smd: 6(1.525,-0.5) 7(1.525,0) 8(1.525,0.5) 14(-1.525,0.5) 15(-1.525,0) 16(-1.525,-0.5)
LQFP128-16X16-4-1_6H
  rect 0.203x1.499 smd: 1(-6.2,-7.85) 2(-5.8,-7.85) 3(-5.4,-7.85) 4(-5,-7.85) 5(-4.6,-7.85) 6(-4.2,-7.85) 7(-3.8,-7.85) 8(-3.4,-7.85) 9(-3,-7.85) 10(-2.6,-7.85) 11(-2.2,-7.85) 12(-1.8,-7.85) 13(-1.4,-7.85) 14(-1,-7.85) 15(-0.6,-7.85) 16(-0.2,-7.85) 17(0.2,-7.85) 18(0.6,-7.85) 19(1,-7.85) 20(1.4,-7.85) 21(1.8,-7.85) 22(2.2,-7.85) 23(2.6,-7.85) 24(3,-7.85) 25(3.4,-7.85) 26(3.8,-7.85) 27(4.2,-7.85) 28(4.6,-7.85) 29(5,-7.85) 30(5.4,-7.85) 31(5.8,-7.85) 32(6.2,-7.85) 65(6.2,7.85) 66(5.8,7.85) 67(5.4,7.85) 68(5,7.85) 69(4.6,7.85) 70(4.2,7.85) 71(3.8,7.85) 72(3.4,7.85) 73(3,7.85) 74(2.6,7.85) 75(2.2,7.85) 76(1.8,7.85) 77(1.4,7.85) 78(1,7.85) 79(0.6,7.85) 80(0.2,7.85) 81(-0.2,7.85) 82(-0.6,7.85) 83(-1,7.85) 84(-1.4,7.85) 85(-1.8,7.85) 86(-2.2,7.85) 87(-2.6,7.85) 88(-3,7.85) 89(-3.4,7.85) 90(-3.8,7.85) 91(-4.2,7.85) 92(-4.6,7.85) 93(-5,7.85) 94(-5.4,7.85) 95(-5.8,7.85) 96(-6.2,7.85)
  rect 1.499x0.203 smd: 33(7.85,-6.2) 34(7.85,-5.8) 35(7.85,-5.4) 36(7.85,-5) 37(7.85,-4.6) 38(7.85,-4.2) 39(7.85,-3.8) 40(7.85,-3.4) 41(7.85,-3) 42(7.85,-2.6) 43(7.85,-2.2) 44(7.85,-1.8) 45(7.85,-1.4) 46(7.85,-1) 47(7.85,-0.6) 48(7.85,-0.2) 49(7.85,0.2) 50(7.85,0.6) 51(7.85,1) 52(7.85,1.4) 53(7.85,1.8) 54(7.85,2.2) 55(7.85,2.6) 56(7.85,3) 57(7.85,3.4) 58(7.85,3.8) 59(7.85,4.2) 60(7.85,4.6) 61(7.85,5) 62(7.85,5.4) 63(7.85,5.8) 64(7.85,6.2) 97(-7.85,6.2) 98(-7.85,5.8) 99(-7.85,5.4) 100(-7.85,5) 101(-7.85,4.6) 102(-7.85,4.2) 103(-7.85,3.8) 104(-7.85,3.4) 105(-7.85,3) 106(-7.85,2.6) 107(-7.85,2.2) 108(-7.85,1.8) 109(-7.85,1.4) 110(-7.85,1) 111(-7.85,0.6) 112(-7.85,0.2) 113(-7.85,-0.2) 114(-7.85,-0.6) 115(-7.85,-1) 116(-7.85,-1.4) 117(-7.85,-1.8) 118(-7.85,-2.2) 119(-7.85,-2.6) 120(-7.85,-3) 121(-7.85,-3.4) 122(-7.85,-3.8) 123(-7.85,-4.2) 124(-7.85,-4.6) 125(-7.85,-5) 126(-7.85,-5.4) 127(-7.85,-5.8) 128(-7.85,-6.2)
NGFF-NASE0-S6701-TS40-KE-SMT
  round 1.194 hole 1.194 unplated: (-10,0)
  round 1.702 hole 1.702 unplated: (10,0)
  rect 0.305x1.549 smd: 1(-9.25,5.275) 2(-9,-2.275) 3(-8.75,5.275) 4(-8.5,-2.275) 5(-8.25,5.275) 6(-8,-2.275) 7(-7.75,5.275) 8(-7.5,-2.275) 9(-7.25,5.275) 10(-7,-2.275) 11(-6.75,5.275) 12(-6.5,-2.275) 13(-6.25,5.275) 14(-6,-2.275) 15(-5.75,5.275) 16(-5.5,-2.275) 17(-5.25,5.275) 18(-5,-2.275) 19(-4.75,5.275) 20(-4.5,-2.275) 21(-4.25,5.275) 22(-4,-2.275) 23(-3.75,5.275) 32(-1.5,-2.275) 33(-1.25,5.275) 34(-1,-2.275) 35(-0.75,5.275) 36(-0.5,-2.275) 37(-0.25,5.275) 38(0,-2.275) 39(0.25,5.275) 40(0.5,-2.275) 41(0.75,5.275) 42(1,-2.275) 43(1.25,5.275) 44(1.5,-2.275) 45(1.75,5.275) 46(2,-2.275) 47(2.25,5.275) 48(2.5,-2.275) 49(2.75,5.275) 50(3,-2.275) 51(3.25,5.275) 52(3.5,-2.275) 53(3.75,5.275) 54(4,-2.275) 55(4.25,5.275) 56(4.5,-2.275) 57(4.75,5.275) 58(5,-2.275) 59(5.25,5.275) 60(5.5,-2.275) 61(5.75,5.275) 62(6,-2.275) 63(6.25,5.275) 64(6.5,-2.275) 65(6.75,5.275) 66(7,-2.275) 67(7.25,5.275) 68(7.5,-2.275) 69(7.75,5.275) 70(8,-2.275) 71(8.25,5.275) 72(8.5,-2.275) 73(8.75,5.275) 74(9,-2.275) 75(9.25,5.275)
  rect 1.194x2.743 smd: 76(-10.35,4.5) 77(10.35,4.5)
POWER-5_2X5_55-1_27-5P
  rect 0.66x0.508 smd: 1(2.755,-1.905) 2(2.755,-0.635) 3(2.755,0.635) 4(2.755,1.905)
  custom 1.15x1.15 smd: 5(0,0)
QFN10-3X3-5-16P
  rect 0.279x0.838 smd: 1(-1,-1.475) 2(-0.5,-1.475) 3(0,-1.475) 4(0.5,-1.475) 5(1,-1.475) 6(1,1.475) 7(0.5,1.475) 8(0,1.475) 9(-0.5,1.475) 10(-1,1.475)
  custom 0.413x0.413 smd: 11(0,0)
  round 0.508 hole 0.254: 12(-0.75,0.5) 13(0.75,0.5) 14(-0.75,-0.5) 15(0.75,-0.5) 16(0,0)
QFN12-3X3-45-0_6H
  rect 0.229x0.787 smd: 1(-0.619,-1.5) 6(-0.619,1.5)
  rect 0.229x1.346 smd: 2(0.101,-1.225) 3(1.001,-1.225)
  rect 0.229x2.286 smd: 4(0.551,0.76)
  rect 0.229x2.261 smd: 5(-0.169,0.76)
  rect 0.787x0.229 smd: 7(-1.5,1.125) 8(-1.5,0.675) 9(-1.5,0.225) 10(-1.5,-0.225) 11(-1.5,-0.675) 12(-1.5,-1.125)
QFN23-4X4-5-25P
  rect 0.254x0.787 smd: 1(-1.25,-2) 2(-0.75,-2) 3(-0.25,-2) 4(0.25,-2) 5(0.75,-2) 6(1.25,-2) 12(1.25,2) 13(0.75,2) 14(0.25,2) 15(-0.25,2) 16(-0.75,2) 17(-1.25,2)
  rect 0.787x0.254 smd: 7(2,-1.25) 8(2,-0.75) 9(2,-0.25) 10(2,0.75) 11(2,1.25) 18(-2,1.25) 19(-2,0.75) 20(-2,0.25) 21(-2,-0.25) 22(-2,-0.75) 23(-2,-1.25)
  rect 2.591x1.295 smd: 24(0,-0.65)
  rect 2.591x0.889 smd: 25(0,0.85)
QFN24-4X4-5-25P-ALC5629
  rect 0.305x0.991 smd: 1(-1.25,-2.1) 2(-0.75,-2.1) 3(-0.25,-2.1) 4(0.25,-2.1) 5(0.75,-2.1) 6(1.25,-2.1) 13(1.25,2.1) 14(0.75,2.1) 15(0.25,2.1) 16(-0.25,2.1) 17(-0.75,2.1) 18(-1.25,2.1)
  rect 0.991x0.305 smd: 7(2.1,-1.25) 8(2.1,-0.75) 9(2.1,-0.25) 10(2.1,0.25) 11(2.1,0.75) 12(2.1,1.25) 19(-2.1,1.25) 20(-2.1,0.75) 21(-2.1,0.25) 22(-2.1,-0.25) 23(-2.1,-0.75) 24(-2.1,-1.25)
  rect 2.261x2.261 smd: 25(0,0)
QFN28-4X4-4-29P-RT5041A
  rect 0.203x0.991 smd: 1(-1.2,-2.1) 2(-0.8,-2.1) 3(-0.4,-2.1) 4(0,-2.1) 5(0.4,-2.1) 6(0.8,-2.1) 7(1.2,-2.1) 15(1.2,2.1) 16(0.8,2.1) 17(0.4,2.1) 18(0,2.1) 19(-0.4,2.1) 20(-0.8,2.1) 21(-1.2,2.1)
  rect 0.991x0.203 smd: 8(2.1,-1.2) 9(2.1,-0.8) 10(2.1,-0.4) 11(2.1,0) 12(2.1,0.4) 13(2.1,0.8) 14(2.1,1.2) 22(-2.1,1.2) 23(-2.1,0.8) 24(-2.1,0.4) 25(-2.1,0) 26(-2.1,-0.4) 27(-2.1,-0.8) 28(-2.1,-1.2)
  rect 2.388x2.388 smd: 29(0,0)
QFN28-4X4-4-38P
  custom 0.05x0.05 smd: 1(-1.2,-2) 2(-0.8,-2) 3(-0.4,-2) 4(0,-2) 5(0.4,-2) 6(0.8,-2) 7(1.2,-2) 8(2,-1.2) 9(2,-0.8) 10(2,-0.4) 11(2,0) 12(2,0.4) 13(2,0.8) 14(2,1.2) 15(1.2,2) 16(0.8,2) 17(0.4,2) 18(0,2) 19(-0.4,2) 20(-0.8,2) 21(-1.2,2) 22(-2,1.2) 23(-2,0.8) 24(-2,0.4) 25(-2,0) 26(-2,-0.4) 27(-2,-0.8) 28(-2,-1.2)
  rect 2.591x2.591 smd: 29(0,0)
  round 0.508 hole 0.254: 30(-1,-1) 31(0,-1) 32(1,-1) 33(1,0) 34(1,1) 35(0,1) 36(-1,1) 37(-1,0) 38(0,0)
QFN32-4X4-4-33P-0_9H
  custom 0.051x0.051 smd: 1(-1.4,-2.1) 8(1.4,-2.1) 9(2.1,-1.4) 16(2.1,1.4) 17(1.4,2.1) 24(-1.4,2.1) 25(-2.1,1.4) 32(-2.1,-1.4)
  rect 0.203x0.991 smd: 2(-1,-2.1) 3(-0.6,-2.1) 4(-0.2,-2.1) 5(0.2,-2.1) 6(0.6,-2.1) 7(1,-2.1) 18(1,2.1) 19(0.6,2.1) 20(0.2,2.1) 21(-0.2,2.1) 22(-0.6,2.1) 23(-1,2.1)
  rect 0.991x0.203 smd: 10(2.1,-1) 11(2.1,-0.6) 12(2.1,-0.2) 13(2.1,0.2) 14(2.1,0.6) 15(2.1,1) 26(-2.1,1) 27(-2.1,0.6) 28(-2.1,0.2) 29(-2.1,-0.2) 30(-2.1,-0.6) 31(-2.1,-1)
  rect 2.692x2.692 smd: 33(0,0)
QFN32-5X5-5-33P-0_85H
  rect 0.305x0.991 smd: 1(-1.75,-2.6) 2(-1.25,-2.6) 3(-0.75,-2.6) 4(-0.25,-2.6) 5(0.25,-2.6) 6(0.75,-2.6) 7(1.25,-2.6) 8(1.75,-2.6) 17(1.75,2.6) 18(1.25,2.6) 19(0.75,2.6) 20(0.25,2.6) 21(-0.25,2.6) 22(-0.75,2.6) 23(-1.25,2.6) 24(-1.75,2.6)
  rect 0.991x0.305 smd: 9(2.6,-1.75) 10(2.6,-1.25) 11(2.6,-0.75) 12(2.6,-0.25) 13(2.6,0.25) 14(2.6,0.75) 15(2.6,1.25) 16(2.6,1.75) 25(-2.6,1.75) 26(-2.6,1.25) 27(-2.6,0.75) 28(-2.6,0.25) 29(-2.6,-0.25) 30(-2.6,-0.75) 31(-2.6,-1.25) 32(-2.6,-1.75)
  rect 3.505x3.505 smd: 33(0,0)
QFN48-6X6-4-49P-ALC280
  rect 0.203x0.991 smd: 1(-2.2,-3.1) 2(-1.8,-3.1) 3(-1.4,-3.1) 4(-1,-3.1) 5(-0.6,-3.1) 6(-0.2,-3.1) 7(0.2,-3.1) 8(0.6,-3.1) 9(1,-3.1) 10(1.4,-3.1) 11(1.8,-3.1) 12(2.2,-3.1) 25(2.2,3.1) 26(1.8,3.1) 27(1.4,3.1) 28(1,3.1) 29(0.6,3.1) 30(0.2,3.1) 31(-0.2,3.1) 32(-0.6,3.1) 33(-1,3.1) 34(-1.4,3.1) 35(-1.8,3.1) 36(-2.2,3.1)
  rect 0.991x0.203 smd: 13(3.1,-2.2) 14(3.1,-1.8) 15(3.1,-1.4) 16(3.1,-1) 17(3.1,-0.6) 18(3.1,-0.2) 19(3.1,0.2) 20(3.1,0.6) 21(3.1,1) 22(3.1,1.4) 23(3.1,1.8) 24(3.1,2.2) 37(-3.1,2.2) 38(-3.1,1.8) 39(-3.1,1.4) 40(-3.1,1) 41(-3.1,0.6) 42(-3.1,0.2) 43(-3.1,-0.2) 44(-3.1,-0.6) 45(-3.1,-1) 46(-3.1,-1.4) 47(-3.1,-1.8) 48(-3.1,-2.2)
  rect 4.394x4.394 smd: 49(0,0)
QFN48-6X6-4-49P-PS8409
  custom 0.05x0.05 smd: 1(-2.2,-2.975) 2(-1.8,-2.975) 3(-1.4,-2.975) 4(-1,-2.975) 5(-0.6,-2.975) 6(-0.2,-2.975) 7(0.2,-2.975) 8(0.6,-2.975) 9(1,-2.975) 10(1.4,-2.975) 11(1.8,-2.975) 12(2.2,-2.975) 13(2.975,-2.2) 14(2.975,-1.8) 15(2.975,-1.4) 16(2.975,-1) 17(2.975,-0.6) 18(2.975,-0.2) 19(2.975,0.2) 20(2.975,0.6) 21(2.975,1) 22(2.975,1.4) 23(2.975,1.8) 24(2.975,2.2) 25(2.2,2.975) 26(1.8,2.975) 27(1.4,2.975) 28(1,2.975) 29(0.6,2.975) 30(0.2,2.975) 31(-0.2,2.975) 32(-0.6,2.975) 33(-1,2.975) 34(-1.4,2.975) 35(-1.8,2.975) 36(-2.2,2.975) 37(-2.975,2.2) 38(-2.975,1.8) 39(-2.975,1.4) 40(-2.975,1) 41(-2.975,0.6) 42(-2.975,0.2) 43(-2.975,-0.2) 44(-2.975,-0.6) 45(-2.975,-1) 46(-2.975,-1.4) 47(-2.975,-1.8) 48(-2.975,-2.2)
  rect 4.496x4.496 smd: 49(0,0)
